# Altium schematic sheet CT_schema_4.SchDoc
size 283 x 147 mm
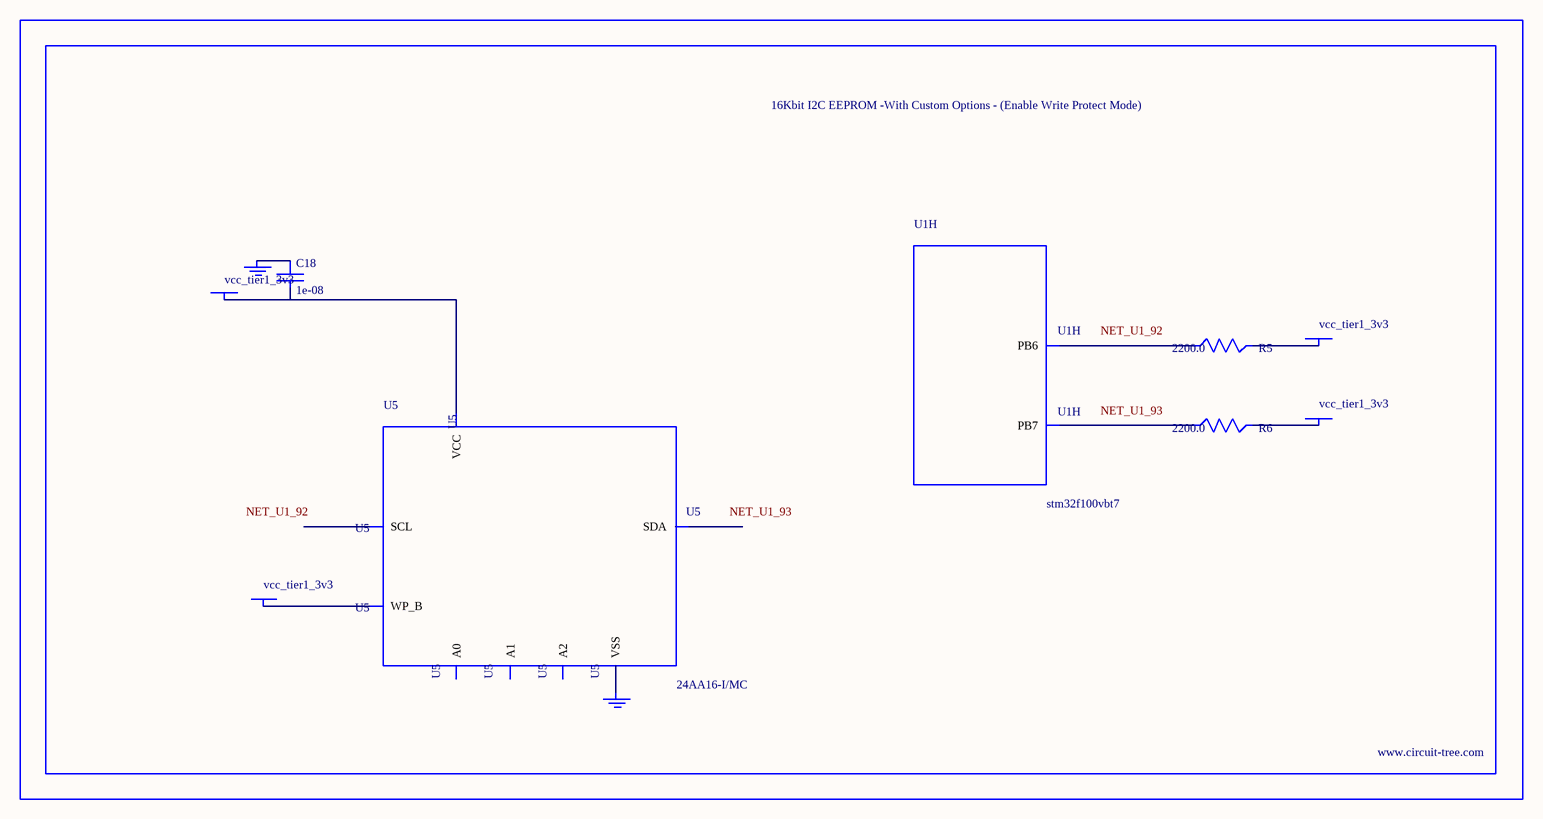
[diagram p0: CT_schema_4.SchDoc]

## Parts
BORDER3  (no value)
C18  1e-08  [C0402]
GND_INSTANCE_3_0  (no value)
GND_INSTANCE_3_1  (no value)
POWER_INSTANCE_3_0  vcc_tier1_3v3
POWER_INSTANCE_3_1  vcc_tier1_3v3
POWER_INSTANCE_3_2  vcc_tier1_3v3
POWER_INSTANCE_3_3  vcc_tier1_3v3
R5  2200.0  [R0603]
R6  2200.0  [R0603]
U1  stm32f100vbt7  [LQFP100]  (part H of 9)
U5  24AA16-I/MC  [TDFN-8/6MM]

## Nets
NetC18_1: C18.1 GND_INSTANCE_3_0.0(GND)
NetC18_2: C18.2 POWER_INSTANCE_3_1.0(PWR) U5.8(VCC)
NetGND_INSTANCE_3_1_0: GND_INSTANCE_3_1.0(GND) U5.4(VSS)
NetPOWER_INSTANCE_3_0_0: POWER_INSTANCE_3_0.0(PWR) U5.7(WP_B)
NetPOWER_INSTANCE_3_2_0: POWER_INSTANCE_3_2.0(PWR) R5.2
NetPOWER_INSTANCE_3_3_0: POWER_INSTANCE_3_3.0(PWR) R6.2
NetR5_1: R5.1 U1.92(PB6)
NetR6_1: R6.1 U1.93(PB7)

Not connected (* = marked no-connect by the designer): U5 1(A0) 2(A1) 3(A2) 5(SDA) 6(SCL)

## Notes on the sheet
- Labels drawn without touching a wire or pin: NET_U1_92, NET_U1_93

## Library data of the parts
BORDER3 = BORDER_PAGE3
C18 = C0402C103K3RAC
GND_INSTANCE_3_0 GND_INSTANCE_3_1 = GND
POWER_INSTANCE_3_0-POWER_INSTANCE_3_3 = PWR
R5 R6 = RC0603JR-072K2L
